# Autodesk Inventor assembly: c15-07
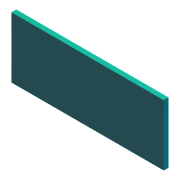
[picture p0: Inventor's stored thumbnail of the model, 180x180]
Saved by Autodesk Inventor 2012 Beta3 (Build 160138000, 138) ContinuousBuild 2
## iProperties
Created: 2011-02
Part Number: c15-07
Document SubType Name: Assembly
Designer: Beta-8540w
RuleStatus: InUse
Author: Beta-8540w
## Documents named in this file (4)
- C:\Inventor 2012 Essentials\Assemblies\Chapter 15\c15-07.iam
- C:\Inventor 2012 Essentials\Parts\Chapter 15\c15-24.ipt
- C:\Inventor 2012 Essentials\Parts\Chapter 15\c15-25.ipt
- C:\Inventor 2012 Essentials\Parts\Chapter 15\c15-26.ipt
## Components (5 placed, 3 different names)
1. c15-24:1 — Flush:3, Flush:6, Flush:9, Flush:12
2. c15-25:1 — Flush:3
3. c15-25:2 — Flush:6
4. c15-26:1 — Flush:9
5. c15-26:2 — Flush:12
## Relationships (4: Flush 4)
- Flush:3: c15-24:1 ↔ c15-25:1
- Flush:6: c15-24:1 ↔ c15-25:2
- Flush:9: c15-24:1 ↔ c15-26:1
- Flush:12: c15-24:1 ↔ c15-26:2
## Named parameters: drawer_width = 508 mm, drawer_height = 203.2 mm, pull_width = 76.2 mm, edge_band_thickness = 1 mm
